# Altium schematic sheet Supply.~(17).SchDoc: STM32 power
size A4; Date: Not used; ApprovedBy: Not used; CheckedBy: Not used; Author: Not used; CompanyName: STMicroelectronics; DrawnBy: Not used; Engineer: Not used; Organization: Not used; Address1: Not used; Address2: Not used; Address3: Not used; Address4: Not used; DocumentNumber: Not used; Revision: Not used; SheetNumber: 4; SheetTotal: 5
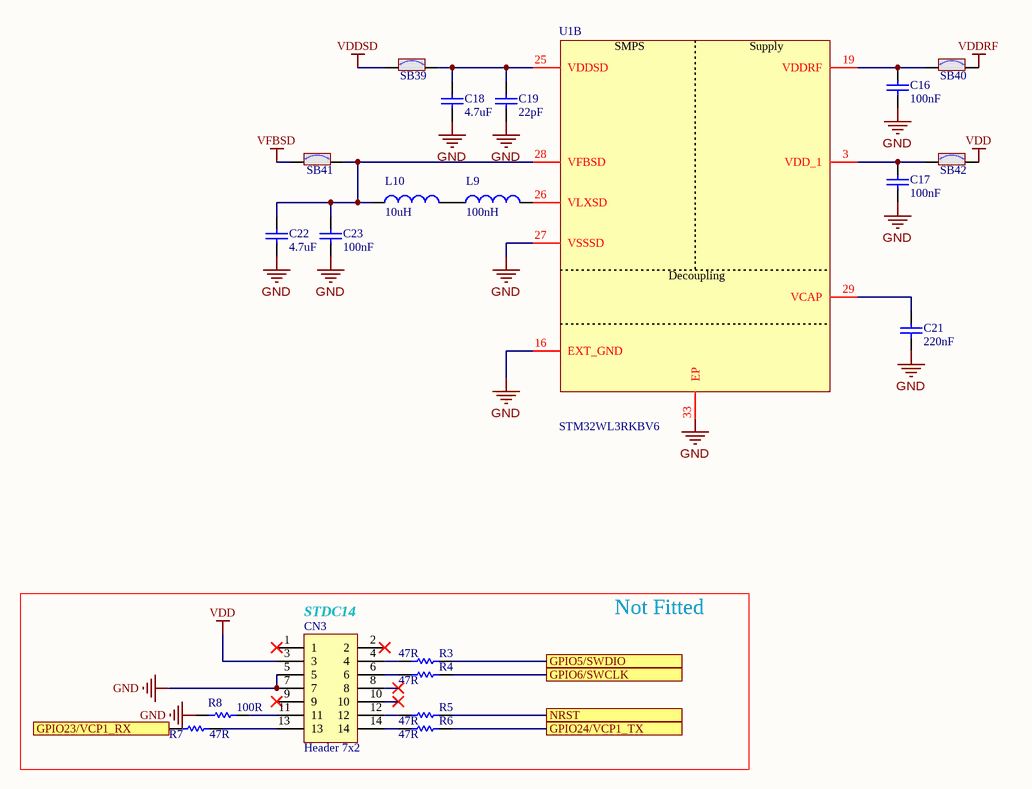
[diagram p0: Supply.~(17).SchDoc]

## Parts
C16  value 100nF  [C0402]  (hidden comment: Capacitor)
C17  value 100nF  [C0402]  (hidden comment: Capacitor)
C18  value 4.7uF  [C0402]  (hidden comment: Capacitor)
C19  value 22pF  [C0402_H0P5]  (hidden comment: Capacitor)
C21  value 220nF  [C0402]  (hidden comment: Capacitor)
C22  value 4.7uF  [C0402]  (hidden comment: Capacitor)
C23  value 100nF  [C0402]  (hidden comment: Capacitor)
CN3  Header 7x2  [CON_SAMTEC_FTSH-107-01-L-DV-K]
L9  value 100nH  [IND_0402_MURATA_LQG15HSXXXX02_H0P5]  (hidden comment: Inductor)
L10  value 10uH  [IND_0805_MURATA_LQM21]  (hidden comment: Inductor)
R3  value 47R  [R0402]  (hidden comment: Resistor)
R4  value 47R  [R0402]  (hidden comment: Resistor)
R5  value 47R  [R0402]  (hidden comment: Resistor)
R6  value 47R  [R0402]  (hidden comment: Resistor)
R7  value 47R  [R0402]  (hidden comment: Resistor)
R8  value 100R  [R0402]  (hidden comment: Resistor)
SB39  SB_ON  [SOLDER-BRIDGE_R0402-0R]  (value not drawn)
SB40  SB_ON  [SOLDER-BRIDGE_R0402-0R]  (value not drawn)
SB41  SB_ON  [SOLDER-BRIDGE_R0402-0R]  (value not drawn)
SB42  SB_ON  [SOLDER-BRIDGE_R0402-0R]  (value not drawn)
U1  value STM32WL3RKBV6  [ICC_VFQFPN32-EPAD_5X5_P050]  (hidden comment: IC_STM32WL3R)  (part B of 3)

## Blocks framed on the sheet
Not Fitted: CN3 R3-R8

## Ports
GPIO5/SWDIO, GPIO6/SWCLK, GPIO23/VCP1_RX, GPIO24/VCP1_TX, NRST

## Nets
GND: C16.1 C17.1 C18.1 C19.2 C21.1 C22.1 C23.2 CN3.5 CN3.7 R8.1 U1.16(EXT_GND) U1.27(VSSSD) U1.33(EP)
VDD: CN3.3 SB42.2
VDDRF: SB40.2
VDDSD: SB39.1
VFBSD: SB41.1
GPIO5/SWDIO: R3.2 ; port GPIO5/SWDIO
GPIO6/SWCLK: R4.2 ; port GPIO6/SWCLK
GPIO23/VCP1_RX: R7.1 ; port GPIO23/VCP1_RX
GPIO24/VCP1_TX: R6.2 ; port GPIO24/VCP1_TX
NRST: R5.2 ; port NRST
NetC16_2: C16.2 SB40.1 U1.19(VDDRF)
NetC17_2: C17.2 SB42.1 U1.3(VDD_1)
NetC18_2: C18.2 C19.1 SB39.2 U1.25(VDDSD)
NetC21_2: C21.2 U1.29(VCAP)
NetC22_2: C22.2 C23.1 L10.1 SB41.2 U1.28(VFBSD)
NetCN3_4: CN3.4 R3.1
NetCN3_6: CN3.6 R4.1
NetCN3_11: CN3.11 R8.2
NetCN3_12: CN3.12 R5.1
NetCN3_13: CN3.13 R7.2
NetCN3_14: CN3.14 R6.1
NetL9_1: L9.1 L10.2
NetL9_2: L9.2 U1.26(VLXSD)

Not connected (* = marked no-connect by the designer): CN3 1* 2* 8* 9* 10*

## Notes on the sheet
- (near CN3) STDC14

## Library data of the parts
C16 C17 C23 = MCD-03442: Capacitor, MLCC, 100nF, 25V, X7R, +/-10%, 0402, T=0.5mm; Part_Preference: Recommended; Manufacturer: MURATA; Manufacturer_Part_Number: GRM155R71E104KE14D; Order_Code_RS: 247-8011; ShowFields: YES; ID: 5558; Component_Country_Of_Origin: China, Japan, Philippines, Singapore
C18 C22 = MCD-03431: Capacitor, MLCC, 4.7uF, 10V, X5R, +/-20%, 0402, T=0.5mm; Part_Preference: Recommended; Manufacturer: MURATA; Manufacturer_Part_Number: GRM155R61A475MEAAD; Order_Code_RS: 172-6870; ShowFields: YES; ID: 5547; Component_Country_Of_Origin: China, Japan, Philippines, Singapore
C19 = MCD-03948: Capacitor, MLCC, 22pF, 50V, C0G, +/-5%, 0402, T=0.5mm; Part_Preference: Recommended; Manufacturer: MURATA; Manufacturer_Part_Number: GJM1555C1H220JB01; Order_Code_RS: 185-3422; ShowFields: YES; ID: 6064; Component_Country_Of_Origin: Japan, Singapore
C21 = MCD-03077: Capacitor, MLCC, 220nF, 35V, X6S, +/-10%, 0402, T=0.5mm; Part_Preference: Recommended; Manufacturer: MURATA; Manufacturer_Part_Number: GRM155C8YA224KE01D; Component_Country_Of_Origin: Japan; ShowFields: YES; ID: 5193
CN3 = MCD-01531: Header, 7x2, 1.27mm, VR, T=5.97mm, FTSH series STDC14 without Alignment Pin; Part_Type: Connector; Part_Preference: Recommended; Manufacturer: SAMTEC; Manufacturer_Part_Number: FTSH-107-01-L-DV-K; Order_Code_RS: 179-9021; Component_Country_Of_Origin: China, Costa Rica, Malaysia, USA, Vietnam; ShowFields: YES; ID: 3631
L9 = MCD-03453: Inductor, 100nH, +/-5%, 200mA, 1R25, 0402, T=0.5mm; Part_Preference: Recommended; Manufacturer: MURATA; Manufacturer_Part_Number: LQG15HSR10J02; Order_Code_RS: 792-6369; ShowFields: YES; ID: 5569; Component_Country_Of_Origin: Japan
L10 = MCD-02317: Inductor, 10uH, +/-20%, 100mA, 0R5, 0805, T=1.45mm; Part_Preference: Recommended; Manufacturer: MURATA; Manufacturer_Part_Number: LQM21FN100M80L; Order_Code_RS: 786-7074; Component_Country_Of_Origin: Japan°°; ShowFields: YES; ID: 4423
R3-R7 = MCD-00481: Resistor, 47R, 0402, +/-1%, 1/16W; Manufacturer_Part_Number: RC0402FR-0747RL; Manufacturer: YAGEO; Part_Preference: Recommended; Component_Country_Of_Origin: China; ShowFields: YES; ID: 2796
R8 = MCD-00067: Resistor, 100R, 0402, +/- 1%, 1/16W; Part_Preference: Recommended; Manufacturer: YAGEO; Manufacturer_Part_Number: RC0402FR-07100RL; Order_Code_RS: 9239111; Component_Country_Of_Origin: China; ShowFields: YES; ID: 2527
SB39-SB42 = MCD-01618: Resistor, 0R, SB0402, 5%, 0.063W; Part_Preference: Recommended; Manufacturer: YAGEO; Manufacturer_Part_Number: RC0402JR-070RL; Order_Code_RS: 618-5804; Component_Country_Of_Origin: China; ShowFields: YES; ID: 3718
U1 = MCD-04431: MCU, ARM Cortex-M0 32-bit, 128KB Flash, 16KB SRAM, With Crypto; Part_Type: IC; Part_Preference: Recommended; Manufacturer: STMICROELECTRONICS; ShowFields: YES; ID: 6547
